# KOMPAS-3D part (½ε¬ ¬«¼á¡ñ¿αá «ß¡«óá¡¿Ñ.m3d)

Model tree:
1. Эскиз:1
2. Операция выдавливания:1
     Расстояние 1 = 5; Расстояние 2 = 0.3
3. Скругление:1
     Радиус = 14
4. Эскиз:3
5. Вырезать элемент выдавливания:1
     Расстояние 1 = 4.5
6. Эскиз:4
7. Вырезать элемент выдавливания:2
     Расстояние 1 = 7.5
8. Эскиз:14
9. Вырезать элемент выдавливания:3
     Расстояние 1 = 4
10. Эскиз:15
11. Операция выдавливания:10
     Расстояние 1 = 7.5; Расстояние 2 = 9.5
12. Скругление:2
     Радиус = 1
13. Эскиз:16
14. Вырезать элемент выдавливания:4
     Расстояние 1 = 33.6595
15. Эскиз:17
16. Операция выдавливания:11
     Расстояние 1 = 11; Расстояние 2 = 9.5
17. Смещенная плоскость:1
     Расстояние = 9.9
18. Эскиз:19
19. Операция выдавливания:12
     Расстояние 1 = 0.5; Расстояние 2 = 0.5
20. Эскиз:20
21. Операция выдавливания:13
     Расстояние 1 = 3; Расстояние 2 = 0.5
22. Эскиз:21
23. Операция выдавливания:14
     Расстояние 1 = 2; Расстояние 2 = 0.5
24. Эскиз:22
25. Операция выдавливания:15
     Расстояние 1 = 9.5; Расстояние 2 = 0.5
26. Эскиз:23
27. Операция выдавливания:16
     Расстояние 1 = 8; Расстояние 2 = 8
28. Эскиз:24
29. Операция выдавливания:17
     Расстояние 1 = 11; Расстояние 2 = 8
30. Эскиз:25
31. Вырезать элемент выдавливания:5
     Расстояние 1 = 34.7374
32. Эскиз:26
33. Вырезать элемент выдавливания:6
     Расстояние 1 = 7
34. Эскиз:27
35. Вырезать элемент выдавливания:7
     Расстояние 1 = 1.27
36. Эскиз:28
37. Операция выдавливания:18
     Расстояние 1 = 21; Расстояние 2 = 8
38. Эскиз:29
39. Вырезать элемент выдавливания:8
     Расстояние 1 = 1.27
40. Эскиз:30
41. Операция выдавливания:19
     Расстояние 1 = 21; Расстояние 2 = 4
42. Эскиз:31
43. Операция выдавливания:20
     Расстояние 1 = 9.5; Расстояние 2 = 28
44. Эскиз:32
45. Операция выдавливания:21
     Расстояние 1 = 10; Расстояние 2 = 1
46. Эскиз:33
47. Вырезать элемент выдавливания:9
     Расстояние 2 = 2; Расстояние 1 = 37.27
48. Эскиз:34
49. Операция выдавливания:22
     Расстояние 1 = 0.5; Расстояние 2 = 1
50. Скругление:3
     Радиус = 0.1
51. Эскиз:35
52. Операция выдавливания:23
     Расстояние 1 = 2; Расстояние 2 = 1
53. Эскиз:36
54. Операция выдавливания:24
     Расстояние 1 = 0.5; Расстояние 2 = 1
55. Эскиз:37
56. Операция выдавливания:25
     Расстояние 1 = 0.2; Расстояние 2 = 1
57. Скругление:4
     Радиус = 0.1
58. Эскиз:38
59. Операция выдавливания:26
     Расстояние 1 = 2; Расстояние 2 = 1
60. Скругление:6
     Радиус = 0.3
61. Скругление:9
     Радиус = 0.3
62. Скругление:10
     Радиус = 0.2
63. Ломаная:1
64. Перпендикулярная плоскость:1
65. Эскиз:42
66. Кинематическая операция:1
     Толщина стенки 1 = 1; Толщина стенки 2 = 1
67. Скругление:11
     Радиус = 0.2
68. Эскиз:43
69. Вырезать элемент выдавливания:12
     Расстояние 2 = 2; Расстояние 1 = 1
70. Эскиз:44
71. Операция выдавливания:28
     Расстояние 1 = 0.1; Расстояние 2 = 1
72. Эскиз:45
73. Вырезать элемент выдавливания:13
     Расстояние 2 = 2; Расстояние 1 = 1
74. Эскиз:46
75. Операция выдавливания:29
     Расстояние 1 = 1; Расстояние 2 = 1
76. Скругление:12
     Радиус = 0.2
77. Эскиз:47
78. Операция выдавливания:30
     Расстояние 1 = 0.3; Расстояние 2 = 1
79. Эскиз:48
80. Операция выдавливания:31
     Расстояние 1 = 1; Расстояние 2 = 1
81. Скругление:13
     Радиус = 0.2
82. Эскиз:49
83. Операция выдавливания:32
     Расстояние 1 = 0.3; Расстояние 2 = 1
84. Ломаная:2
85. Эскиз:51
86. Операция выдавливания:33
     Расстояние 1 = 0.5; Расстояние 2 = 1
87. Эскиз:52
88. Операция выдавливания:34
     Расстояние 1 = 0.5; Расстояние 2 = 1
89. Эскиз:53
90. Операция выдавливания:35
     Расстояние 1 = 2.5; Расстояние 2 = 1
91. Скругление:14
     Радиус = 0.5
92. Эскиз:54
93. Вырезать элемент выдавливания:14
     Расстояние 2 = 2; Расстояние 1 = 2
94. Перпендикулярная плоскость:3
95. Эскиз:55
96. Кинематическая операция:3
     Толщина стенки 1 = 1; Толщина стенки 2 = 1
97. Эскиз:56
98. Операция выдавливания:36
     Расстояние 1 = 0.2; Расстояние 2 = 18
99. Эскиз:57
100. Вырезать элемент выдавливания:15
     Расстояние 1 = 0.1
101. Эскиз:59
102. Вырезать элемент выдавливания:16
     Расстояние 1 = 0.2
103. Эскиз:60
104. Операция выдавливания:37
     Расстояние 1 = 0.2; Расстояние 2 = 18
105. Скругление:15
     Радиус = 0.2
106. Эскиз:61
107. Операция выдавливания:38
     Расстояние 1 = 20.2; Расстояние 2 = 18
108. Скругление:16
     Радиус = 0.2
109. Эскиз:62
110. Операция выдавливания:39
     Расстояние 1 = 6; Расстояние 2 = 18
111. Эскиз:63
112. Операция выдавливания:40
     Расстояние 1 = 6; Расстояние 2 = 18
113. Скругление:18
     Радиус = 1
114. Скругление:19
     Радиус = 1
115. Скругление:21
     Радиус = 0.5
116. Эскиз:64
117. Вырезать элемент выдавливания:17
     Расстояние 1 = 2
118. Эскиз:65
119. Вырезать элемент выдавливания:18
     Расстояние 1 = 2
120. Эскиз:66
121. Операция выдавливания:41
     Расстояние 1 = 0.2; Расстояние 2 = 18
122. Скругление:22
     Радиус = 0.1
123. Скругление:23
     Радиус = 0.1
124. Эскиз:67
125. Операция выдавливания:42
     Расстояние 1 = 2; Расстояние 2 = 6
126. Скругление:24
     Радиус = 2
127. Скругление:25
     Радиус = 1
128. Эскиз:68
129. Операция выдавливания:43
     Расстояние 1 = 2; Угол 1 = 6; Расстояние 2 = 6
130. Скругление:26
     Радиус = 1
131. Сплайновая форма:2
132. Эскиз:69
133. Вырезать элемент выдавливания:19
     Расстояние 1 = 6; Угол 1 = 9

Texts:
  люк командира основание
  stalker61
  Сплав АЛ8  ГОСТ 1583-93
